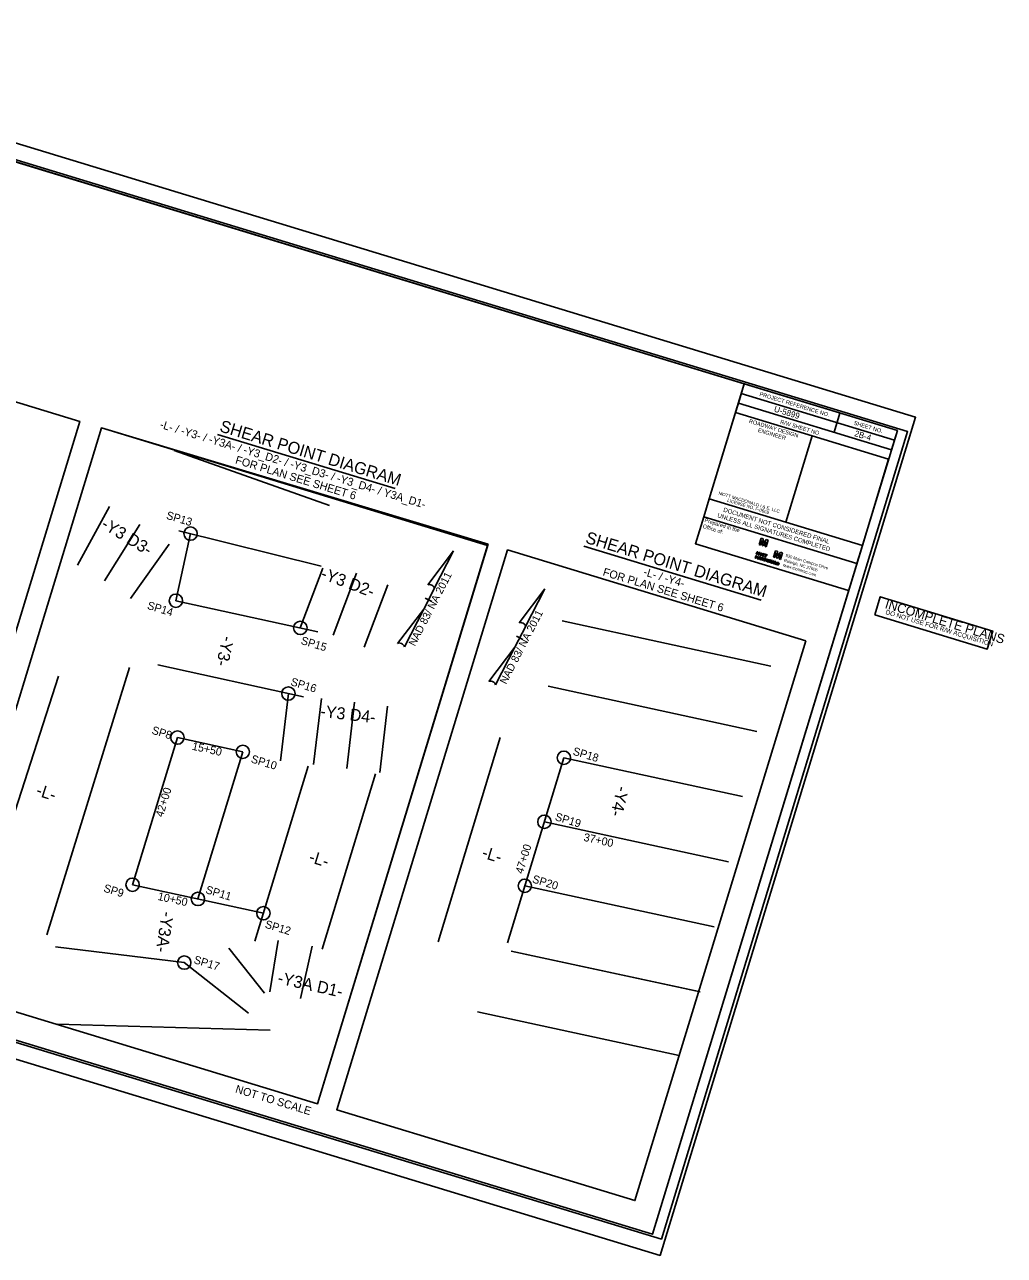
# Model space of a CAD drawing. Extents: x 1619199 to 1620423, y 897643 to 898566.
# Drawn here: x 1619689 to 1620423, y 897643 to 898566 of the extents above; entities that cross this region are included whole.
import ezdxf

# ---------------------------------------------------------------- set-up
doc = ezdxf.new("R2010")
doc.units = 0
for name, color, linetype in [('Default', 7, 'Continuous'), ('Old_Level_2', 7, 'Continuous'), ('Old_Level_42', 7, 'Continuous'), ('Old_Level_45', 7, 'Continuous'), ('Pattern 5', 7, 'Continuous'), ('Prop North Arrow NAD83 for Plan Sheets CELL', 7, 'Continuous'), ('Sheet Data Field CELL', 7, 'Continuous'), ('Sheet Plan CELL', 7, 'Continuous'), ('Sheet Plot Border Inside CELL', 7, 'Continuous'), ('Sheet Plot Border Outside CELL', 7, 'Continuous'), ('Sheet Sticker Exception Certification CELL', 7, 'Continuous'), ('Sheet Sticker Incomplete CELL', 7, 'Continuous')]:
    doc.layers.add(name, color=color, linetype=linetype)

msp = doc.modelspace()

# ---------------------------------------------------------------- linework, layer by layer
at = {"layer": 'Default'}
for p, q in [((1619833.43, 898258.31), (1619966.39, 898217.79)), ((1619917.39, 898205.17), (1619800.83, 898246.23)), ((1619728.36, 898160.37), (1619752.34, 898204.24)), ((1619748.56, 898148.49), (1619775.23, 898190.79)), ((1619911.14, 898159.48), (1619804.31, 898186.17)), ((1619768.14, 898135.28), (1619797.11, 898176.04)), ((1619802.16, 898133.67), (1619813.16, 898183.96)), ((1620107.9, 898174.66), (1620240.97, 898134.1)), ((1619912.22, 898158.12), (1619895.42, 898113.27)), ((1619937.49, 898154.32), (1619920.1, 898107.87)), ((1619960.91, 898145.56), (1619943.37, 898098.73)), ((1619908.43, 898110.43), (1619802.16, 898133.67)), ((1620248.11, 898084.58), (1620091.74, 898118.47)), ((1619767.47, 898083.48), (1619705.49, 897883.15)), ((1619897.74, 898061.58), (1619788.48, 898085.48)), ((1619714.16, 898076.98), (1619664.97, 897924.73)), ((1620237.52, 898035.71), (1620081.15, 898069.61)), ((1619886.45, 898064.05), (1619880.55, 898013.68)), ((1619911.2, 898060.43), (1619905.38, 898010.77)), ((1619936.03, 898057.52), (1619930.21, 898007.86)), ((1619960.86, 898054.61), (1619955.04, 898004.95)), ((1619803.31, 898031.05), (1619769.67, 897920.7)), ((1619852.31, 898020.34), (1619803.31, 898031.05)), ((1619852.31, 898020.34), (1619818.68, 897910)), ((1619901.32, 898009.62), (1619861.28, 897878.27)), ((1620092.96, 898015.89), (1620050.63, 897877.04)), ((1620226.92, 897986.85), (1620092.96, 898015.89)), ((1619951.87, 898003.96), (1619911.76, 897872.4)), ((1620216.33, 897937.98), (1620078.33, 897967.9)), ((1619867.69, 897899.3), (1619769.67, 897920.7)), ((1620205.74, 897889.12), (1620063.7, 897919.91)), ((1619808.46, 897862.26), (1619712, 897874.01)), ((1619841.76, 897873.04), (1619868.57, 897839.46)), ((1619878.77, 897878.9), (1619872.57, 897840.39)), ((1619904.3, 897874.67), (1619895.52, 897835.28)), ((1620194.03, 897840.5), (1620053.42, 897870.98)), ((1619808.46, 897862.26), (1619856.66, 897824.32)), ((1620179.4, 897792.51), (1620028.19, 897825.28)), ((1619872.73, 897811.67), (1619713.03, 897816.04))]:
    msp.add_line(p, q, dxfattribs=at)
for points in [[(1619462.5, 898349.68), (1619730.07, 898268.15), (1619602.5, 897849.59), (1619334.95, 897931.12)], [(1620036.23, 898176.17), (1619908.29, 897756.39), (1619618.7, 897844.65), (1619746.28, 898263.24)], [(1620035.83, 898174.97), (1619908.21, 897756.39), (1619618.7, 897844.65), (1619746.31, 898263.23)], [(1620274.25, 898103.63), (1620146.27, 897683.84), (1619922.76, 897751.98), (1620050.74, 898171.77)]]:
    msp.add_lwpolyline(points, close=True, dxfattribs=at)
for centre in [(1619813.16, 898183.96), (1619802.16, 898133.67), (1619895.42, 898113.27), (1619886.45, 898064.05), (1619803.31, 898031.05), (1619852.31, 898020.34), (1620092.96, 898015.89), (1620078.33, 897967.9), (1619769.67, 897920.7), (1620063.7, 897919.91), (1619818.68, 897910), (1619867.69, 897899.3), (1619808.46, 897862.26)]:
    msp.add_circle(centre, 5, dxfattribs=at)
at = {"layer": 'Old_Level_2'}
for p, q in [((1620240.88, 898180.63), (1620239.4, 898175.75)), ((1620239.4, 898175.75), (1620240.43, 898175.44)), ((1620240.43, 898175.44), (1620241.5, 898178.94)), ((1620242.33, 898180.19), (1620240.88, 898180.63)), ((1620241.5, 898178.94), (1620241.51, 898178.94)), ((1620241.51, 898178.94), (1620241.81, 898175.01)), ((1620242.26, 898174.88), (1620244.71, 898177.98)), ((1620242.59, 898176.82), (1620242.33, 898180.19)), ((1620242.58, 898176.77), (1620242.59, 898176.82)), ((1620242.61, 898176.76), (1620242.58, 898176.77)), ((1620242.62, 898176.81), (1620242.61, 898176.76)), ((1620244.72, 898179.46), (1620242.62, 898176.81)), ((1620244.72, 898177.98), (1620243.65, 898174.45)), ((1620244.68, 898174.14), (1620246.16, 898179.02)), ((1620244.71, 898177.98), (1620244.72, 898177.98)), ((1620246.16, 898179.02), (1620244.72, 898179.46)), ((1620236.89, 898167.52), (1620236.32, 898165.65)), ((1620236.71, 898165.53), (1620237.12, 898166.88)), ((1620237.44, 898167.35), (1620236.89, 898167.52)), ((1620237.12, 898166.88), (1620237.13, 898166.87)), ((1620237.13, 898166.87), (1620237.24, 898165.37)), ((1620237.77, 898170.41), (1620237.2, 898168.55)), ((1620237.2, 898168.55), (1620237.59, 898168.43)), ((1620237.42, 898165.31), (1620238.35, 898166.5)), ((1620237.55, 898166.04), (1620237.44, 898167.35)), ((1620238.36, 898167.07), (1620237.55, 898166.04)), ((1620237.59, 898168.43), (1620238, 898169.77)), ((1620238.32, 898170.24), (1620237.77, 898170.41)), ((1620238.37, 898166.49), (1620237.96, 898165.15)), ((1620238, 898169.77), (1620238.01, 898169.77)), ((1620238.01, 898169.77), (1620238.13, 898168.26)), ((1620238.13, 898168.26), (1620238.3, 898168.21)), ((1620238.3, 898168.21), (1620239.24, 898169.39)), ((1620238.43, 898168.94), (1620238.32, 898170.24)), ((1620238.35, 898165.03), (1620238.92, 898166.9)), ((1620238.35, 898166.5), (1620238.37, 898166.49)), ((1620238.92, 898166.9), (1620238.36, 898167.07)), ((1620239.25, 898169.96), (1620238.43, 898168.94)), ((1620239.25, 898169.39), (1620238.84, 898168.04)), ((1620238.84, 898168.04), (1620239.23, 898167.93)), ((1620239.23, 898167.93), (1620239.8, 898169.79)), ((1620239.24, 898169.39), (1620239.25, 898169.39)), ((1620239.8, 898169.79), (1620239.25, 898169.96)), ((1620241.81, 898175.01), (1620242.26, 898174.88)), ((1620243.65, 898174.45), (1620244.68, 898174.14)), ((1620251.56, 898171.16), (1620250.07, 898166.29)), ((1620250.07, 898166.29), (1620251.1, 898165.97)), ((1620251.1, 898165.97), (1620252.17, 898169.48)), ((1620253, 898170.72), (1620251.56, 898171.16)), ((1620252.17, 898169.48), (1620252.18, 898169.47)), ((1620252.18, 898169.47), (1620252.49, 898165.55)), ((1620252.93, 898165.41), (1620255.38, 898168.52)), ((1620253.26, 898167.35), (1620253, 898170.72)), ((1620253.25, 898167.31), (1620253.26, 898167.35)), ((1620253.28, 898167.3), (1620253.25, 898167.31)), ((1620253.29, 898167.34), (1620253.28, 898167.3)), ((1620255.39, 898170), (1620253.29, 898167.34)), ((1620255.4, 898168.51), (1620254.32, 898164.99)), ((1620255.35, 898164.68), (1620256.84, 898169.55)), ((1620255.38, 898168.52), (1620255.4, 898168.51)), ((1620256.84, 898169.55), (1620255.39, 898170)), ((1620236.32, 898165.65), (1620236.71, 898165.53)), ((1620237.24, 898165.37), (1620237.42, 898165.31)), ((1620237.96, 898165.15), (1620238.35, 898165.03)), ((1620242.38, 898164.22), (1620242.11, 898164.48)), ((1620242.37, 898165.18), (1620242.74, 898165.23)), ((1620242.84, 898164.64), (1620242.57, 898163.75)), ((1620242.57, 898163.75), (1620243.42, 898163.49)), ((1620243.14, 898165.61), (1620242.84, 898164.64)), ((1620243.07, 898163.98), (1620243.42, 898165.15)), ((1620243.53, 898163.84), (1620243.07, 898163.98)), ((1620243.99, 898165.35), (1620243.14, 898165.61)), ((1620243.42, 898165.15), (1620243.88, 898165.01)), ((1620252.5, 898161.7), (1620252.22, 898160.8)), ((1620252.22, 898160.8), (1620253.07, 898160.54)), ((1620252.49, 898165.55), (1620252.93, 898165.41)), ((1620252.79, 898162.67), (1620252.5, 898161.7)), ((1620252.72, 898161.04), (1620253.07, 898162.21)), ((1620253.18, 898160.9), (1620252.72, 898161.04)), ((1620253.64, 898162.41), (1620252.79, 898162.67)), ((1620253.07, 898162.21), (1620253.54, 898162.07)), ((1620254.32, 898164.99), (1620255.35, 898164.68))]:
    msp.add_line(p, q, dxfattribs=at)
for points in [[(1620238.57, 898164.96), (1620239.02, 898164.83), (1620239.23, 898165.1), (1620240.04, 898164.86), (1620240.06, 898164.51), (1620240.5, 898164.38), (1620240.35, 898166.46), (1620239.86, 898166.61), (1620238.57, 898164.96)], [(1620242.04, 898168.73), (1620242.57, 898168.57), (1620242.11, 898167.05), (1620242.51, 898166.93), (1620242.98, 898168.45), (1620243.51, 898168.28), (1620243.62, 898168.63), (1620242.14, 898169.08), (1620242.04, 898168.73)], [(1620243.75, 898168.21), (1620244.29, 898168.05), (1620243.82, 898166.53), (1620244.23, 898166.4), (1620244.69, 898167.93), (1620245.23, 898167.76), (1620245.33, 898168.1), (1620243.86, 898168.55), (1620243.75, 898168.21)], [(1620239.44, 898165.42), (1620239.99, 898166.13), (1620240.04, 898165.23), (1620239.44, 898165.42)], [(1620247.5, 898163.56), (1620247.52, 898163.56), (1620248.04, 898162.08), (1620248.42, 898161.96), (1620248.99, 898163.83), (1620248.6, 898163.95), (1620248.24, 898162.77), (1620247.72, 898164.21), (1620247.33, 898164.33), (1620246.76, 898162.47), (1620247.13, 898162.35), (1620247.5, 898163.56)], [(1620248.66, 898161.89), (1620249.1, 898161.75), (1620249.32, 898162.03), (1620250.12, 898161.79), (1620250.15, 898161.44), (1620250.58, 898161.3), (1620250.43, 898163.39), (1620249.94, 898163.54), (1620248.66, 898161.89)], [(1620249.53, 898162.34), (1620250.07, 898163.06), (1620250.12, 898162.16), (1620249.53, 898162.34)], [(1620252, 898160.87), (1620252.1, 898161.2), (1620251.29, 898161.45), (1620251.76, 898162.98), (1620251.37, 898163.1), (1620250.8, 898161.24), (1620252, 898160.87)]]:
    msp.add_lwpolyline(points, dxfattribs=at)
msp.add_arc((1620253.36, 898161.48), 0.975, 253.04954, 73.04954, dxfattribs=at)
for centre, major_axis, ratio in [((1620240.78, 898168.47), (0.284, 0.932), 0.993118), ((1620240.78, 898168.47), (0.186, 0.607), 0.916103), ((1620245.79, 898163.78), (0.284, 0.932), 0.993118), ((1620245.79, 898163.78), (0.186, 0.607), 0.916103)]:
    msp.add_ellipse(centre, major_axis=major_axis, ratio=ratio, dxfattribs=at)
for centre, major_axis, ratio, start_param, end_param in [((1620241.8, 898165), (0.284, 0.932), 0.993118, 5.246647, 10.366427), ((1620241.8, 898165), (0.186, 0.607), 0.916103, 5.276876, 10.296021), ((1620243.7, 898164.42), (-0.284, -0.932), 0.930276, 0, 3.141593), ((1620243.71, 898164.43), (-0.177, -0.582), 0.900832, 0, 3.141593), ((1620253.36, 898161.48), (-0.177, -0.582), 0.900832, 0, 3.141593)]:
    msp.add_ellipse(centre, major_axis=major_axis, ratio=ratio, start_param=start_param, end_param=end_param, dxfattribs=at)
at = {"layer": 'Old_Level_42'}
msp.add_lwpolyline([(1620306.45, 898141.39), (1620191.63, 898176.39), (1620197.81, 898196.64)], dxfattribs=at)
at = {"layer": 'Pattern 5'}
for p, q in [((1620248.11, 898084.58), (1620091.74, 898118.47)), ((1620237.52, 898035.71), (1620081.15, 898069.61)), ((1620045.3, 898031), (1619998.64, 897877.96)), ((1620226.92, 897986.85), (1620092.96, 898015.89)), ((1620216.33, 897937.98), (1620078.33, 897967.9)), ((1620205.74, 897889.12), (1620063.7, 897919.91)), ((1620195.15, 897840.25), (1620053.42, 897870.98))]:
    msp.add_line(p, q, dxfattribs=at)
at = {"layer": 'Prop North Arrow NAD83 for Plan Sheets CELL'}
for p, q in [((1619991.06, 898145.7), (1620010.29, 898170.99)), ((1620010.32, 898170.97), (1619995.56, 898142.28)), ((1620010.32, 898170.97), (1620010.29, 898170.99)), ((1620010.32, 898170.97), (1620010.29, 898170.99)), ((1619987.9, 898127.4), (1619995.99, 898143.12)), ((1619995.56, 898142.28), (1619995.98, 898143.09)), ((1620059.4, 898117.19), (1620078.64, 898142.48)), ((1620078.67, 898142.46), (1620063.9, 898113.77)), ((1620078.67, 898142.46), (1620078.64, 898142.48)), ((1620078.67, 898142.46), (1620078.64, 898142.48)), ((1619989.08, 898135.59), (1619989.05, 898135.61)), ((1619991.21, 898134.5), (1619989.08, 898135.59)), ((1619989.11, 898135.58), (1619993.92, 898133.11)), ((1619987.9, 898127.4), (1619968.3, 898101.62)), ((1619973.4, 898099.14), (1619987.9, 898127.4)), ((1620056.24, 898098.89), (1620064.34, 898114.61)), ((1620063.9, 898113.77), (1620064.32, 898114.58)), ((1620057.43, 898107.09), (1620057.4, 898107.1)), ((1620059.56, 898105.99), (1620057.43, 898107.09)), ((1620057.46, 898107.07), (1620062.26, 898104.6)), ((1620056.24, 898098.89), (1620036.64, 898073.11)), ((1620041.74, 898070.64), (1620056.24, 898098.89))]:
    msp.add_line(p, q, dxfattribs=at)
for centre, start_param, end_param in [((1619993.39, 898144.12), 0.216388, 2.908219), ((1620061.73, 898115.62), 0.216388, 2.908219), ((1619970.79, 898100.21), 0.201328, 3.141593), ((1620039.13, 898071.7), 0.201328, 3.141593)]:
    msp.add_ellipse(centre, major_axis=(2.53, -1.32), ratio=0.461098, start_param=start_param, end_param=end_param, dxfattribs=at)
at = {"layer": 'Sheet Plan CELL'}
for p, q in [((1620225.96, 898289.06), (1620340.77, 898254.06)), ((1620223.77, 898281.86), (1620221.59, 898274.7)), ((1620223.77, 898281.86), (1620338.58, 898246.88)), ((1620299.9, 898274.35), (1620295.55, 898259.99)), ((1620279.01, 898257.19), (1620259.34, 898192.65))]:
    msp.add_line(p, q, dxfattribs=at)
for points in [[(1620342.99, 898261.25), (1619482.06, 898523.65), (1619298.39, 897921.02), (1620159.3, 897658.63)], [(1619298.39, 897921.02), (1619482.05, 898523.64), (1620228.16, 898296.26), (1620201.92, 898210.13), (1620316.72, 898175.13), (1620159.3, 897658.63)], [(1620228.16, 898296.26), (1620342.99, 898261.25), (1620338.58, 898246.88), (1620223.77, 898281.86)], [(1620221.59, 898274.7), (1620279.01, 898257.19), (1620259.33, 898192.62), (1620201.92, 898210.13)], [(1620279.01, 898257.19), (1620336.4, 898239.71), (1620316.72, 898175.13), (1620259.33, 898192.62)]]:
    msp.add_lwpolyline(points, close=True, dxfattribs=at)
at = {"layer": 'Sheet Plot Border Inside CELL'}
msp.add_lwpolyline([(1619209.86, 897946.43), (1620166.03, 897655.01), (1620350.58, 898260.5), (1619394.41, 898551.93)], close=True, dxfattribs=at)
at = {"layer": 'Sheet Plot Border Outside CELL'}
msp.add_lwpolyline([(1619198.9, 897937.22), (1620165.12, 897642.73), (1620356.66, 898271.19), (1619390.44, 898565.68)], close=True, dxfattribs=at)
at = {"layer": 'Sheet Sticker Exception Certification CELL'}
for p, q in [((1620197.81, 898196.64), (1620201.92, 898210.13)), ((1620201.92, 898210.13), (1620316.72, 898175.14)), ((1620312.61, 898161.65), (1620197.81, 898196.64)), ((1620316.72, 898175.13), (1620312.61, 898161.65))]:
    msp.add_line(p, q, dxfattribs=at)
at = {"layer": 'Sheet Sticker Incomplete CELL'}
msp.add_lwpolyline([(1620325.99, 898123.16), (1620330.1, 898136.64), (1620414.47, 898110.93), (1620410.36, 898097.44)], close=True, dxfattribs=at)

# ---------------------------------------------------------------- texts
at = {"layer": 'Default'}
for s, height, rotation, p in [('-L- / -Y3- / -Y3A- / -Y3_D2- / -Y3_D3- / -Y3_D4- / Y3A_D1-', 6, 343.04954, (1619789.63, 898263.4)), ('SHEAR POINT DIAGRAM', 9, 343.04954, (1619834.34, 898260.76)), ('FOR PLAN SEE SHEET 6', 6, 343.04954, (1619846.21, 898236.74)), ('-Y3 D3-', 9, 328.69239, (1619745.48, 898188.78)), ('SP13', 6, 343.04954, (1619794.45, 898195.24)), ('SHEAR POINT DIAGRAM', 9, 343.04954, (1620108.55, 898177.19)), ('-Y3 D2-', 9, 339.46776, (1619910.13, 898150.53)), ('FOR PLAN SEE SHEET 6', 6, 343.04954, (1620121.71, 898152.72)), ('-L- / -Y4-', 6, 343.04954, (1620152.16, 898152.85)), ('SP14', 6, 343.04954, (1619780.19, 898127.63)), ('-Y3-', 9, 257.6616, (1619837.1, 898107.78)), ('SP15', 6, 343.04954, (1619895.36, 898101.33)), ('SP16', 6, 343.04954, (1619887.71, 898070.39)), ('-Y3 D4-', 9, 353.31262, (1619910.12, 898046.57)), ('SP8', 6, 343.04954, (1619783.54, 898034.05)), ('15+50', 6, 347.6616, (1619813.86, 898021.99)), ('SP18', 6, 343.04954, (1620099.18, 898018.32)), ('SP10', 6, 343.04954, (1619857.98, 898012.52)), ('-L-', 9, 342.36918, (1619696.68, 897987.88)), ('42+00', 6, 73.04884, (1619792.39, 897970.94)), ('-Y4-', 9, 257.02279, (1620132.95, 897995.14)), ('SP19', 6, 343.04954, (1620085.89, 897969.17)), ('37+00', 6, 347.6616, (1620107.37, 897953.63)), ('-L-', 9, 343.04884, (1619901.18, 897937.87)), ('-L-', 9, 343.04884, (1620030.87, 897941.16)), ('47+00', 6, 73.04884, (1620062.19, 897928.44)), ('SP20', 6, 343.04954, (1620068.82, 897922.48)), ('SP9', 6, 343.04954, (1619747.49, 897915.62)), ('SP11', 6, 343.04954, (1619823.95, 897914.48)), ('10+50', 6, 347.68291, (1619788.16, 897909.33)), ('-Y3A-', 9, 261.41462, (1619791.68, 897901.05)), ('SP12', 6, 343.04954, (1619868.43, 897888.58)), ('SP17', 6, 343.04954, (1619815.06, 897861.97)), ('-Y3A D1-', 9, 347.43469, (1619877.83, 897846.79)), ('NOT TO SCALE', 6, 343.04954, (1619846.22, 897764.98))]:
    msp.add_text(s, height=height, rotation=rotation, dxfattribs=at).set_placement(p)
at = {"layer": 'Old_Level_2'}
for s, height, p in [('Prepared in the ', 2.8912, (1620198.15, 898192.78)), ('Office of:', 2.891, (1620196.79, 898188.34)), ('930 Main Campus Drive', 2.25, (1620258.86, 898166.73)), ('www.mottmac.com', 2.25, (1620256.67, 898159.54)), ('Raleigh, NC 27606', 2.25, (1620257.73, 898163.03))]:
    msp.add_text(s, height=height, rotation=343.04954, dxfattribs=at).set_placement(p)
at = {"layer": 'Old_Level_45'}
for s, p in [('MOTT MACDONALD I & E, LLC', (1620208.72, 898213.34)), (' LICENSE NO. F-0669', (1620214.32, 898208.28))]:
    msp.add_text(s, height=2.4107, rotation=343.04954, dxfattribs=at).set_placement(p)
at = {"layer": 'Prop North Arrow NAD83 for Plan Sheets CELL'}
for rotation, p in [(62.76967, (1619981.32, 898099.09)), (62.7692, (1620049.66, 898070.58))]:
    msp.add_text('NAD 83/ NA 2011', height=5.7375, rotation=rotation, dxfattribs=at).set_placement(p)
at = {"layer": 'Sheet Data Field CELL'}
for s, p in [('U-5899', (1620250.09, 898275.57)), ('2B-4', (1620310.41, 898257.23))]:
    msp.add_text(s, height=4.5, rotation=343.04955, dxfattribs=at).set_placement(p)
at = {"layer": 'Sheet Plan CELL'}
for s, height, p in [('PROJECT REFERENCE NO.', 3.0001, (1620239.37, 898287.37)), ('ROADWAY DESIGN', 3.0001, (1620231.43, 898267.12)), ('R/W SHEET NO.', 3.0001, (1620254.88, 898266.62)), ('SHEET NO.', 3, (1620310.04, 898265.76)), ('ENGINEER', 3, (1620238.14, 898260.34))]:
    msp.add_text(s, height=height, rotation=343.04955, dxfattribs=at).set_placement(p)
at = {"layer": 'Sheet Sticker Exception Certification CELL'}
for s, p in [('DOCUMENT NOT CONSIDERED FINAL', (1620212.2, 898200.51)), ('UNLESS ALL SIGNATURES COMPLETED', (1620207.75, 898196.35))]:
    msp.add_text(s, height=3.3, rotation=343.04954, dxfattribs=at).set_placement(p)
at = {"layer": 'Sheet Sticker Incomplete CELL'}
for s, height, p in [('INCOMPLETE PLANS', 6.912, (1620333.18, 898128.31)), ('DO NOT USE FOR R/W ACQUISITION', 3.456, (1620333.83, 898123.75))]:
    msp.add_text(s, height=height, rotation=343.04954, dxfattribs=at).set_placement(p)

doc.saveas('drawing.dxf')
